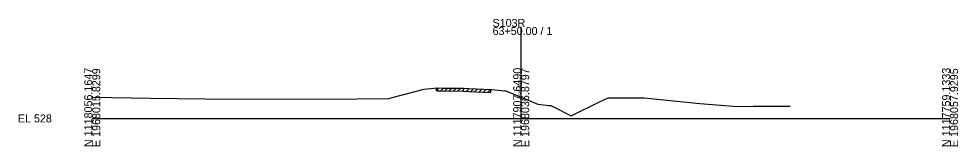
# Model space of a CAD drawing. Extents: x 974 to 1303, y 990 to 10019.
# Drawn here: x 974.3 to 1302.8, y 5990.3 to 6034.8 of the extents above; entities that cross this region are included whole.
import ezdxf

# ---------------------------------------------------------------- set-up
doc = ezdxf.new("R2010")
doc.units = 0
for name, color, linetype in [('Level 10', 7, 'Continuous'), ('Level 60', 7, 'Continuous'), ('Level 61', 7, 'Continuous'), ('Level 63', 7, 'Continuous')]:
    doc.layers.add(name, color=color, linetype=linetype)

msp = doc.modelspace()

# ---------------------------------------------------------------- linework, layer by layer
at = {"layer": 'Level 60'}
for p, q in [((1107.07, 6007.85), (1116.09, 6010.25)), ((1116.09, 6010.25), (1117.2, 6010.33)), ((1117.2, 6010.33), (1120.66, 6010.64)), ((1120.66, 6010.64), (1122.39, 6010.61)), ((1122.39, 6010.61), (1129.84, 6010.56)), ((1129.84, 6010.56), (1131.56, 6010.45)), ((1131.56, 6010.45), (1139.61, 6010.04)), ((1139.61, 6010.04), (1144.25, 6009.65)), ((1144.25, 6009.65), (1144.67, 6009.62)), ((1144.67, 6009.62), (1145.45, 6009.29)), ((1145.45, 6009.29), (1150, 6007.41)), ((1000, 6007.44), (1020.39, 6007.11)), ((1020.39, 6007.11), (1039.53, 6006.85)), ((1039.53, 6006.85), (1057.57, 6006.72)), ((1057.57, 6006.72), (1092.61, 6006.81)), ((1092.61, 6006.81), (1103.71, 6006.98)), ((1103.71, 6006.98), (1107.07, 6007.85)), ((1150, 6007.41), (1155.86, 6005.01)), ((1167.47, 6000.94), (1177.4, 6005.77)), ((1177.4, 6005.77), (1180.37, 6007.17)), ((1180.37, 6007.17), (1183.45, 6007.24)), ((1183.45, 6007.24), (1193.04, 6007.18)), ((1193.04, 6007.18), (1212.43, 6005.2)), ((1155.86, 6005.01), (1159.63, 6004.55)), ((1159.63, 6004.55), (1160.33, 6004.47)), ((1160.33, 6004.47), (1161.12, 6004.17)), ((1161.12, 6004.17), (1167.47, 6000.94)), ((1212.43, 6005.2), (1225.62, 6004.1)), ((1225.62, 6004.1), (1231.14, 6004.27)), ((1231.14, 6004.27), (1244.12, 6004.32))]:
    msp.add_line(p, q, dxfattribs=at)
at = {"layer": 'Level 61'}
for p, q in [((1120.35, 6009.61), (1121.36, 6010.63)), ((1120.35, 6009.61), (1120.35, 6010.61)), ((1120.35, 6009.61), (1120.66, 6009.64)), ((1120.66, 6009.64), (1122.39, 6009.61)), ((1121.85, 6009.62), (1122.84, 6010.6)), ((1122.39, 6009.61), (1129.84, 6009.56)), ((1123.35, 6009.6), (1124.34, 6010.59)), ((1124.85, 6009.59), (1125.84, 6010.58)), ((1126.35, 6009.58), (1127.34, 6010.57)), ((1127.85, 6009.57), (1128.84, 6010.56)), ((1129.35, 6009.56), (1130.32, 6010.53)), ((1129.84, 6009.56), (1131.56, 6009.45)), ((1130.85, 6009.5), (1131.8, 6010.44)), ((1131.56, 6009.45), (1139.3, 6009.06)), ((1132.35, 6009.41), (1133.3, 6010.36)), ((1133.85, 6009.34), (1134.8, 6010.29)), ((1135.35, 6009.26), (1136.3, 6010.21)), ((1136.85, 6009.18), (1137.8, 6010.14)), ((1138.35, 6009.11), (1139.3, 6010.06)), ((1139.3, 6010.06), (1139.3, 6009.06))]:
    msp.add_line(p, q, dxfattribs=at)
at = {"layer": 'Level 63'}
for p, q in [((1150, 6000), (1150, 6031.92)), ((1000, 6000), (1150, 6000)), ((1150, 6000), (1300, 6000))]:
    msp.add_line(p, q, dxfattribs=at)

# ---------------------------------------------------------------- texts
at = {"layer": 'Level 10'}
msp.add_text('535.41', height=0.9, rotation=90, dxfattribs=at).set_placement((1149.95, 6007.91))
at = {"layer": 'Level 63'}
for s, p in [('S103R', (1140, 6031.92)), ('63+50.00 / 1', (1140, 6029.12)), ('EL 528', (974, 5998.6))]:
    msp.add_text(s, height=2.8, dxfattribs=at).set_placement(p)
for s, p in [('N 1118056.1647', (1000, 5990)), ('E 1968015.8299', (1002.8, 5990)), ('N 1117907.6490', (1150, 5990)), ('E 1968036.8797', (1152.8, 5990)), ('N 1117759.1333', (1300, 5990)), ('E 1968057.9295', (1302.8, 5990))]:
    msp.add_text(s, height=2.8, rotation=90, dxfattribs=at).set_placement(p)

doc.saveas('drawing.dxf')
